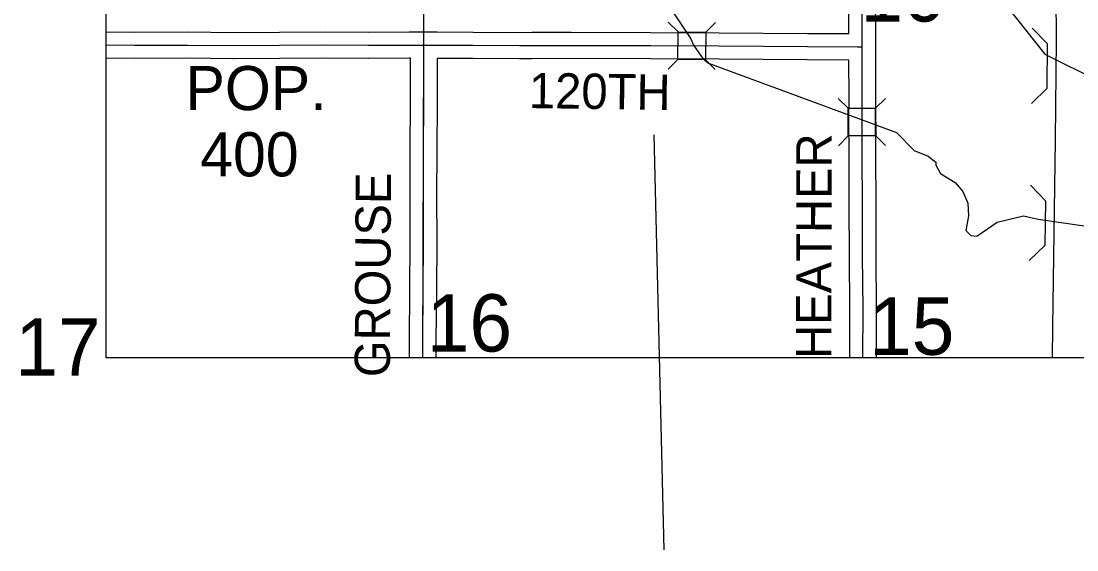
# Model space of a CAD drawing. Extents: x -2251611 to -2054719, y -2227156 to -2099355.
# Drawn here: x -2147976 to -2135345, y -2146614 to -2140286 of the extents above; entities that cross this region are included whole.
import ezdxf

# ---------------------------------------------------------------- set-up
doc = ezdxf.new("R2010")
doc.units = 0
for name, color, linetype in [('dsnTextNote', 7, 'Continuous'), ('tdCoCorpPopTxt', 7, 'Continuous'), ('tdCoHydroRiver', 7, 'Continuous'), ('tdCoInt', 7, 'Continuous'), ('tdCoSecRdTxt', 7, 'Continuous'), ('tdCoSecRteBand', 7, 'Continuous'), ('tdCoSectLinePart', 7, 'Continuous'), ('tdCoSectNmbr', 7, 'Continuous'), ('tdCoStrucDivPri', 7, 'Continuous'), ('tdCoStrucSec', 7, 'Continuous'), ('tdCoSurfAsphalt', 7, 'Continuous'), ('tdCoSurfAsphaltUnbanded', 7, 'Continuous'), ('tdCoSurfGravel', 7, 'Continuous'), ('tdCoTwpBndryShd', 7, 'Continuous')]:
    doc.layers.add(name, color=color, linetype=linetype)

msp = doc.modelspace()

# ---------------------------------------------------------------- linework, layer by layer
at = {"layer": 'dsnTextNote'}
msp.add_lwpolyline([(-2138305, -2118110), (-2124096, -2118110), (-2124096, -2144316), (-2146960, -2144316), (-2146960, -2118110), (-2138305, -2118110)], dxfattribs=at)
at = {"layer": 'tdCoHydroRiver'}
for points in [[(-2140503, -2130185), (-2140506, -2132418), (-2140481, -2132660), (-2140405, -2132826), (-2139244, -2134182), (-2139240, -2135765), (-2139165, -2135881), (-2139156, -2135931), (-2139189, -2136098), (-2139206, -2136140), (-2139170, -2137381), (-2139144, -2137606), (-2139086, -2137698), (-2138977, -2137806), (-2138802, -2138047), (-2138643, -2138280), (-2138342, -2138579), (-2138100, -2138704), (-2137483, -2138735), (-2137350, -2138777), (-2136957, -2139209), (-2136406, -2139824), (-2135729, -2140681), (-2135078, -2141005)], [(-2140360, -2139906), (-2139964, -2140499), (-2139930, -2140574), (-2139820, -2140732), (-2139753, -2140790), (-2137502, -2141618), (-2137293, -2141835), (-2137126, -2141901), (-2137034, -2141976), (-2137034, -2142009), (-2136976, -2142109), (-2136800, -2142217), (-2136708, -2142325), (-2136650, -2142466), (-2136641, -2142616), (-2136674, -2142791), (-2136616, -2142850), (-2136541, -2142858), (-2136299, -2142691), (-2135983, -2142615), (-2135808, -2142656), (-2135258, -2142738)]]:
    msp.add_lwpolyline(points, dxfattribs=at)
at = {"layer": 'tdCoInt'}
msp.add_lwpolyline([(-2135639, -2144316), (-2135635, -2143946), (-2135601, -2141706), (-2135589, -2140509), (-2135600, -2138905), (-2135594, -2138325)], dxfattribs=at)
at = {"layer": 'tdCoSecRteBand'}
for points in [[(-2146960, -2140413), (-2146618, -2140417), (-2145986, -2140414), (-2145985, -2140414), (-2145984, -2140414), (-2145433, -2140421), (-2144340, -2140413), (-2144338, -2140413), (-2144337, -2140413), (-2143817, -2140417), (-2143334, -2140414), (-2143333, -2140414), (-2143333, -2140414), (-2143317, -2140414), (-2143158, -2140415), (-2143000, -2140415), (-2143000, -2140416), (-2143000, -2140416), (-2142999, -2140416), (-2142567, -2140417), (-2142567, -2140417), (-2142567, -2140417), (-2142014, -2140421), (-2141866, -2140420), (-2141395, -2140418), (-2141395, -2140418), (-2141394, -2140418), (-2140444, -2140421), (-2140443, -2140421), (-2140443, -2140421), (-2139624, -2140426), (-2139624, -2140426), (-2139624, -2140426), (-2138569, -2140434), (-2138073, -2140436), (-2138074, -2139981)], [(-2137757, -2139980), (-2137756, -2140436), (-2137756, -2140436), (-2137756, -2140436), (-2137755, -2140436), (-2137755, -2140595), (-2137754, -2141195), (-2137754, -2141196), (-2137754, -2141197), (-2137757, -2141455), (-2137754, -2141883), (-2137754, -2141883), (-2137754, -2141883), (-2137752, -2142492), (-2137752, -2142492), (-2137752, -2142492), (-2137750, -2143093), (-2137745, -2143728), (-2137745, -2143729), (-2137745, -2143729), (-2137746, -2144316)], [(-2143330, -2144316), (-2143330, -2144103), (-2143330, -2144102), (-2143330, -2144102), (-2143325, -2143509), (-2143321, -2142917), (-2143322, -2142393), (-2143322, -2142393), (-2143322, -2142393), (-2143321, -2141818), (-2143321, -2141817), (-2143321, -2141817), (-2143317, -2141277), (-2143317, -2140731), (-2143333, -2140731), (-2143817, -2140734), (-2143818, -2140734), (-2143819, -2140734), (-2144339, -2140730), (-2145432, -2140738), (-2145434, -2140738), (-2145435, -2140738), (-2145986, -2140731), (-2146618, -2140734), (-2146619, -2140734), (-2146620, -2140734), (-2146960, -2140730)], [(-2138063, -2144316), (-2138062, -2143730), (-2138067, -2143095), (-2138067, -2143095), (-2138067, -2143094), (-2138068, -2142493), (-2138071, -2141885), (-2138074, -2141455), (-2138074, -2141454), (-2138074, -2141453), (-2138071, -2141195), (-2138072, -2140754), (-2138072, -2140753), (-2138571, -2140751), (-2138571, -2140751), (-2138571, -2140751), (-2139626, -2140743), (-2140445, -2140738), (-2141394, -2140735), (-2141865, -2140737), (-2142014, -2140738), (-2142015, -2140738), (-2142015, -2140738), (-2142568, -2140734), (-2143000, -2140732), (-2143000, -2141277), (-2143000, -2141278), (-2143000, -2141278), (-2143004, -2141818), (-2143005, -2142393), (-2143004, -2142917), (-2143004, -2142918), (-2143004, -2142919), (-2143008, -2143511), (-2143013, -2144104), (-2143013, -2144316)]]:
    msp.add_lwpolyline(points, dxfattribs=at)
at = {"layer": 'tdCoSectLinePart'}
msp.add_lwpolyline([(-2140408, -2141647), (-2140286, -2146614)], dxfattribs=at)
at = {"layer": 'tdCoStrucDivPri'}
for points in [[(-2135889, -2141272), (-2135700, -2141087), (-2135695, -2140559), (-2135880, -2140370)], [(-2135915, -2143151), (-2135725, -2142968), (-2135716, -2142440), (-2135900, -2142250)]]:
    msp.add_lwpolyline(points, dxfattribs=at)
at = {"layer": 'tdCoStrucSec'}
for p, q in [((-2140117, -2140416), (-2140233, -2140298)), ((-2139786, -2140418), (-2139669, -2140302)), ((-2140119, -2140747), (-2140236, -2140863)), ((-2139788, -2140749), (-2139672, -2140866)), ((-2138083, -2141330), (-2138201, -2141214)), ((-2137753, -2141328), (-2137636, -2141211)), ((-2138081, -2141661), (-2138197, -2141778)), ((-2137751, -2141659), (-2137633, -2141775))]:
    msp.add_line(p, q, dxfattribs=at)
for points in [[(-2140117, -2140416), (-2139786, -2140418), (-2139788, -2140749), (-2140119, -2140747)], [(-2138081, -2141661), (-2138083, -2141330), (-2137753, -2141328), (-2137751, -2141659)]]:
    msp.add_lwpolyline(points, close=True, dxfattribs=at)
at = {"layer": 'tdCoSurfAsphalt'}
msp.add_lwpolyline([(-2143171, -2144316), (-2143171, -2144103), (-2143167, -2143510), (-2143162, -2142918), (-2143163, -2142393), (-2143162, -2141818), (-2143159, -2141277), (-2143159, -2140685), (-2143159, -2140573)], dxfattribs=at)
at = {"layer": 'tdCoSurfAsphaltUnbanded'}
msp.add_lwpolyline([(-2143159, -2140573), (-2143159, -2140259), (-2143155, -2139674), (-2143155, -2139507), (-2143155, -2139320), (-2143155, -2139242), (-2143154, -2138925), (-2143153, -2138767), (-2143156, -2138527), (-2143156, -2138476), (-2143159, -2138212), (-2143158, -2138077), (-2143155, -2137891), (-2143154, -2137783)], dxfattribs=at)
at = {"layer": 'tdCoSurfGravel'}
for points in [[(-2137905, -2144316), (-2137904, -2143729), (-2137909, -2143094), (-2137910, -2142492), (-2137913, -2141884), (-2137915, -2141454), (-2137913, -2141195), (-2137914, -2140595), (-2137914, -2140538), (-2137915, -2139980), (-2137917, -2139326), (-2137919, -2138652), (-2137923, -2138040), (-2137923, -2137962), (-2137926, -2137441), (-2137928, -2136723), (-2137930, -2136072), (-2137928, -2135418), (-2137928, -2135325)], [(-2146960, -2140572), (-2146618, -2140575), (-2145986, -2140573), (-2145434, -2140579), (-2144338, -2140571), (-2143818, -2140575), (-2143333, -2140573), (-2143159, -2140573), (-2143000, -2140574), (-2142568, -2140575), (-2142014, -2140579), (-2141866, -2140579)], [(-2141866, -2140579), (-2141394, -2140577), (-2140444, -2140579), (-2139625, -2140584), (-2138570, -2140592), (-2137969, -2140595), (-2137914, -2140595)]]:
    msp.add_lwpolyline(points, dxfattribs=at)
at = {"layer": 'tdCoTwpBndryShd'}
msp.add_lwpolyline([(-2143082, -2118110), (-2143089, -2119427), (-2143116, -2124764), (-2143141, -2130046), (-2143152, -2135314), (-2143161, -2140573), (-2143174, -2144316)], dxfattribs=at)

# ---------------------------------------------------------------- texts
at = {"layer": 'tdCoCorpPopTxt'}
for s, p in [('POP.', (-2146009, -2141352)), ('400', (-2145834, -2142144))]:
    msp.add_text(s, height=528, dxfattribs=at).set_placement(p)
at = {"layer": 'tdCoSecRdTxt'}
for s, rotation, p in [('120TH', 359.239, (-2141904, -2141327)), ('HEATHER', 89.9521, (-2138282, -2144329)), ('GROUSE', 89.6871, (-2143564, -2144548))]:
    msp.add_text(s, height=422.4, rotation=rotation, dxfattribs=at).set_placement(p)
at = {"layer": 'tdCoSectNmbr'}
for s, rotation, p in [('10', 0.0192, (-2137934, -2140292)), ('16', 0.0183, (-2143123, -2144241)), ('15', 0.0191, (-2137832, -2144280)), ('17', 0.0176, (-2148046, -2144529))]:
    msp.add_text(s, height=686.4, rotation=rotation, dxfattribs=at).set_placement(p)

doc.saveas('drawing.dxf')
